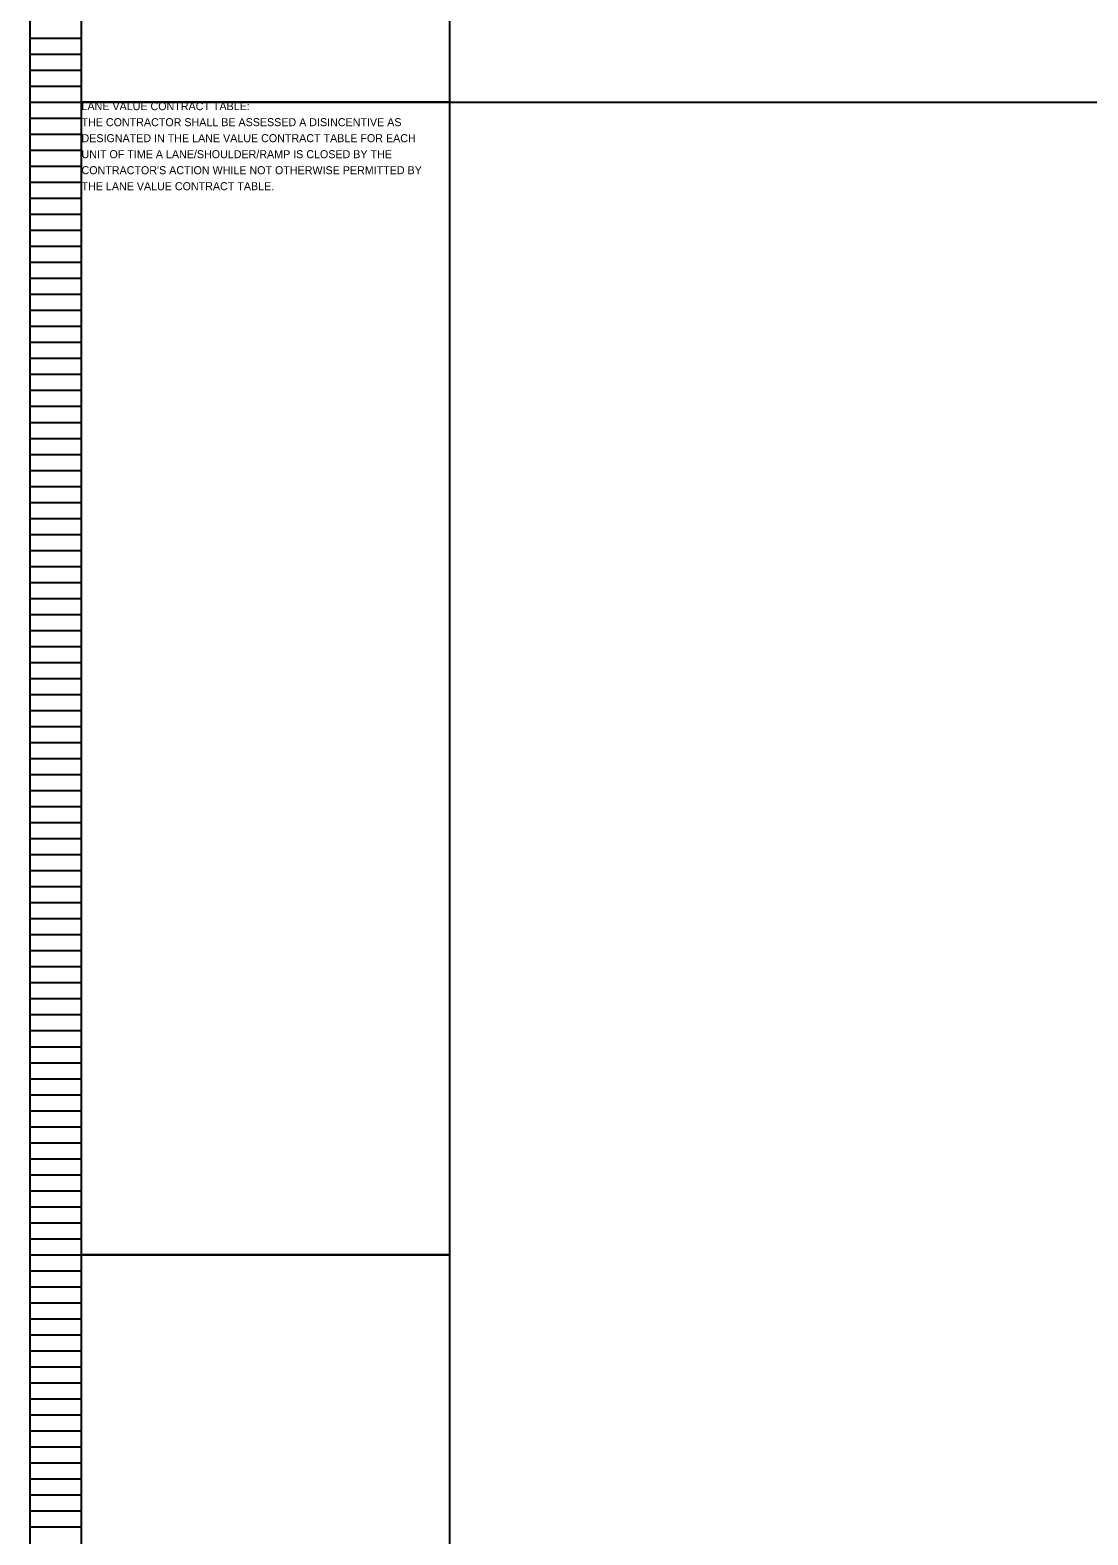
# Model space of a CAD drawing. Extents: x 16463 to 16500, y 5400 to 5823.
# Drawn here: x 16463.05 to 16481.55, y 5717.77 to 5744.09 of the extents above; entities that cross this region are included whole.
import ezdxf

# ---------------------------------------------------------------- set-up
doc = ezdxf.new("R2010")
doc.units = 0
for name, color, linetype in [('SC_Scratch1', 7, 'Continuous'), ('SH_Data', 7, 'Continuous'), ('SH_Text', 7, 'Continuous')]:
    doc.layers.add(name, color=color, linetype=linetype)

msp = doc.modelspace()

# ---------------------------------------------------------------- linework, layer by layer
at = {"layer": 'SC_Scratch1'}
msp.add_line((16470.389, 5742.832), (16500.06, 5742.832), dxfattribs=at)
for points in [[(16463.949, 5762.992), (16470.389, 5762.992), (16470.389, 5742.832), (16463.949, 5742.832)], [(16463.949, 5742.832), (16470.389, 5742.832), (16470.389, 5722.672), (16463.949, 5722.672)], [(16463.949, 5722.672), (16470.389, 5722.672), (16470.389, 5702.512), (16463.949, 5702.512)]]:
    msp.add_lwpolyline(points, close=True, dxfattribs=at)
at = {"layer": 'SH_Data'}
for p, q in [((16463.049, 5742.832), (16463.049, 5762.992)), ((16463.949, 5742.832), (16463.949, 5762.992)), ((16463.049, 5743.952), (16463.949, 5743.952)), ((16463.049, 5743.672), (16463.949, 5743.672)), ((16463.049, 5743.392), (16463.949, 5743.392)), ((16463.049, 5743.112), (16463.949, 5743.112)), ((16463.049, 5722.672), (16463.049, 5742.832)), ((16463.049, 5742.832), (16463.949, 5742.832)), ((16463.049, 5742.832), (16463.949, 5742.832)), ((16463.949, 5722.672), (16463.949, 5742.832)), ((16463.049, 5742.552), (16463.949, 5742.552)), ((16463.049, 5742.272), (16463.949, 5742.272)), ((16463.049, 5741.992), (16463.949, 5741.992)), ((16463.049, 5741.712), (16463.949, 5741.712)), ((16463.049, 5741.432), (16463.949, 5741.432)), ((16463.049, 5741.152), (16463.949, 5741.152)), ((16463.049, 5740.872), (16463.949, 5740.872)), ((16463.049, 5740.592), (16463.949, 5740.592)), ((16463.049, 5740.312), (16463.949, 5740.312)), ((16463.049, 5740.032), (16463.949, 5740.032)), ((16463.049, 5739.752), (16463.949, 5739.752)), ((16463.049, 5739.472), (16463.949, 5739.472)), ((16463.049, 5739.192), (16463.949, 5739.192)), ((16463.049, 5738.912), (16463.949, 5738.912)), ((16463.049, 5738.632), (16463.949, 5738.632)), ((16463.049, 5738.352), (16463.949, 5738.352)), ((16463.049, 5738.072), (16463.949, 5738.072)), ((16463.049, 5737.792), (16463.949, 5737.792)), ((16463.049, 5737.512), (16463.949, 5737.512)), ((16463.049, 5737.232), (16463.949, 5737.232)), ((16463.049, 5736.952), (16463.949, 5736.952)), ((16463.049, 5736.672), (16463.949, 5736.672)), ((16463.049, 5736.392), (16463.949, 5736.392)), ((16463.049, 5736.112), (16463.949, 5736.112)), ((16463.049, 5735.832), (16463.949, 5735.832)), ((16463.049, 5735.552), (16463.949, 5735.552)), ((16463.049, 5735.272), (16463.949, 5735.272)), ((16463.049, 5734.992), (16463.949, 5734.992)), ((16463.049, 5734.712), (16463.949, 5734.712)), ((16463.049, 5734.432), (16463.949, 5734.432)), ((16463.049, 5734.152), (16463.949, 5734.152)), ((16463.049, 5733.872), (16463.949, 5733.872)), ((16463.049, 5733.592), (16463.949, 5733.592)), ((16463.049, 5733.312), (16463.949, 5733.312)), ((16463.049, 5733.032), (16463.949, 5733.032)), ((16463.049, 5732.752), (16463.949, 5732.752)), ((16463.049, 5732.472), (16463.949, 5732.472)), ((16463.049, 5732.192), (16463.949, 5732.192)), ((16463.049, 5731.912), (16463.949, 5731.912)), ((16463.049, 5731.632), (16463.949, 5731.632)), ((16463.049, 5731.352), (16463.949, 5731.352)), ((16463.049, 5731.072), (16463.949, 5731.072)), ((16463.049, 5730.792), (16463.949, 5730.792)), ((16463.049, 5730.512), (16463.949, 5730.512)), ((16463.049, 5730.232), (16463.949, 5730.232)), ((16463.049, 5729.952), (16463.949, 5729.952)), ((16463.049, 5729.672), (16463.949, 5729.672)), ((16463.049, 5729.392), (16463.949, 5729.392)), ((16463.049, 5729.112), (16463.949, 5729.112)), ((16463.049, 5728.832), (16463.949, 5728.832)), ((16463.049, 5728.552), (16463.949, 5728.552)), ((16463.049, 5728.272), (16463.949, 5728.272)), ((16463.049, 5727.992), (16463.949, 5727.992)), ((16463.049, 5727.712), (16463.949, 5727.712)), ((16463.049, 5727.432), (16463.949, 5727.432)), ((16463.049, 5727.152), (16463.949, 5727.152)), ((16463.049, 5726.872), (16463.949, 5726.872)), ((16463.049, 5726.592), (16463.949, 5726.592)), ((16463.049, 5726.312), (16463.949, 5726.312)), ((16463.049, 5726.032), (16463.949, 5726.032)), ((16463.049, 5725.752), (16463.949, 5725.752)), ((16463.049, 5725.472), (16463.949, 5725.472)), ((16463.049, 5725.192), (16463.949, 5725.192)), ((16463.049, 5724.912), (16463.949, 5724.912)), ((16463.049, 5724.632), (16463.949, 5724.632)), ((16463.049, 5724.352), (16463.949, 5724.352)), ((16463.049, 5724.072), (16463.949, 5724.072)), ((16463.049, 5723.792), (16463.949, 5723.792)), ((16463.049, 5723.512), (16463.949, 5723.512)), ((16463.049, 5723.232), (16463.949, 5723.232)), ((16463.049, 5722.952), (16463.949, 5722.952)), ((16463.049, 5702.512), (16463.049, 5722.672)), ((16463.049, 5722.672), (16463.949, 5722.672)), ((16463.049, 5722.672), (16463.949, 5722.672)), ((16463.949, 5702.512), (16463.949, 5722.672)), ((16463.049, 5722.392), (16463.949, 5722.392)), ((16463.049, 5722.112), (16463.949, 5722.112)), ((16463.049, 5721.832), (16463.949, 5721.832)), ((16463.049, 5721.552), (16463.949, 5721.552)), ((16463.049, 5721.272), (16463.949, 5721.272)), ((16463.049, 5720.992), (16463.949, 5720.992)), ((16463.049, 5720.712), (16463.949, 5720.712)), ((16463.049, 5720.432), (16463.949, 5720.432)), ((16463.049, 5720.152), (16463.949, 5720.152)), ((16463.049, 5719.872), (16463.949, 5719.872)), ((16463.049, 5719.592), (16463.949, 5719.592)), ((16463.049, 5719.312), (16463.949, 5719.312)), ((16463.049, 5719.032), (16463.949, 5719.032)), ((16463.049, 5718.752), (16463.949, 5718.752)), ((16463.049, 5718.472), (16463.949, 5718.472)), ((16463.049, 5718.192), (16463.949, 5718.192)), ((16463.049, 5717.912), (16463.949, 5717.912))]:
    msp.add_line(p, q, dxfattribs=at)

# ---------------------------------------------------------------- texts
at = {"layer": 'SH_Text'}
for s, p in [('LANE VALUE CONTRACT TABLE:', (16463.949, 5742.692)), ('THE CONTRACTOR SHALL BE ASSESSED A DISINCENTIVE AS ', (16463.949, 5742.412)), ('DESIGNATED IN THE LANE VALUE CONTRACT TABLE FOR EACH ', (16463.949, 5742.132)), ('UNIT OF TIME A LANE/SHOULDER/RAMP IS CLOSED BY THE ', (16463.949, 5741.852)), ("CONTRACTOR'S ACTION WHILE NOT OTHERWISE PERMITTED BY ", (16463.949, 5741.572)), ('THE LANE VALUE CONTRACT TABLE.', (16463.949, 5741.292))]:
    msp.add_text(s, height=0.14, dxfattribs=at).set_placement(p)

doc.saveas('drawing.dxf')
